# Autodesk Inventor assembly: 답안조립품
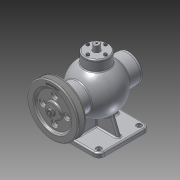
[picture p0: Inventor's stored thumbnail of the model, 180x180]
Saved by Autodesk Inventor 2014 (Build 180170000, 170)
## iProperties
Created: 2015-10
Part Number: 답안조립품
Document SubType Name: Assembly
Designer: youjin07
Author: youjin07
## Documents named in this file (16)
- C:\Users\youjin07\Desktop\451010V1006\답안조립품.iam
- C:\Users\youjin07\Desktop\451010V1006\본체.ipt
- C:\Users\youjin07\Desktop\451010V1006\앞커버.ipt
- C:\Users\youjin07\Desktop\451010V1006\오일실 15 30 7.ipt
- C:\Users\youjin07\Desktop\451010V1006\볼트 M4 x 16.ipt
- C:\Users\youjin07\Desktop\451010V1006\상부커버.ipt
- C:\Users\youjin07\Desktop\451010V1006\볼트 M 4 x 12.ipt
- C:\Users\youjin07\Desktop\451010V1006\뒤커버.ipt
- C:\Users\youjin07\Desktop\451010V1006\베어링- 6202.ipt
- KS B 2023 - 6202 - 15 x 35 x 11 - 7.8.ipt
- C:\Users\youjin07\Desktop\451010V1006\편심축.ipt
- C:\Users\youjin07\Desktop\451010V1006\부시.ipt
- C:\Users\youjin07\Desktop\451010V1006\키 4 x 4 x 12.ipt
- C:\Users\youjin07\Desktop\451010V1006\V-벨트풀리.ipt
- C:\Users\youjin07\Desktop\451010V1006\너트 M8.ipt
- C:\Users\youjin07\Desktop\451010V1006\슬라이드.ipt
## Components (15 placed, 4 different names)
1. KS B 2023 - 6202 - 15 x 35 x 11 - 7.8:1 — 각도:1
2. KS B 2023 - 6202 - 15 x 35 x 11 - 7.8:2 — 각도:2
3. V-벨트풀리:1 — 플러쉬:1
4. ISO 4762 M4 x 16:1
5. ISO 4762 M4 x 16:2
6. ISO 4762 M4 x 16:3
7. ISO 4762 M4 x 16:4
8. KS B 1021 - 에 따름 ISO 1207 - 미터 A  M 4 x 12:1
9. KS B 1021 - 에 따름 ISO 1207 - 미터 A  M 4 x 12:2
10. KS B 1021 - 에 따름 ISO 1207 - 미터 A  M 4 x 12:3
11. KS B 1021 - 에 따름 ISO 1207 - 미터 A  M 4 x 12:4
12. ISO 4762 M4 x 16:5
13. ISO 4762 M4 x 16:6
14. ISO 4762 M4 x 16:7
15. ISO 4762 M4 x 16:8
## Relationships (3: Angle 2, Flush 1)
- 각도:1 [Angle]: KS B 2023 - 6202 - 15 x 35 x 11 - 7.8:1
- 각도:2 [Angle]: KS B 2023 - 6202 - 15 x 35 x 11 - 7.8:2
- 플러쉬:1 [Flush]: V-벨트풀리:1
